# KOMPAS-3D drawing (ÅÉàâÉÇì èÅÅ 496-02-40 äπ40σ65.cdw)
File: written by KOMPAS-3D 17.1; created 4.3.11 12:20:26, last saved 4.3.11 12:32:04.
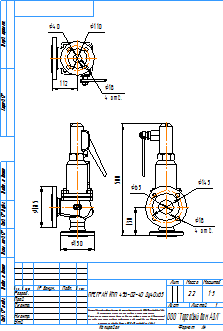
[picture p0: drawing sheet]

Sheet 1: A4, portrait

Title block, sheet 1: name: ПРЕГРАН КПП 496-02-40 Ду40х65; mass: 22; sheets: 1; sheet format: A4; stored path: \\adlc.lan\data\АДЛ_ПКД\3D-модели\ADL production\Предохранительные клапаны ПРЕГРАН\ПРЕГРАН 496\ПРЕГРАН КПП 496-02-40\KOMPAS 2D\ПРЕГРАН КПП 496-02-40 Ду40х65.cdw

Views: Спереди 1, Проекционный вид 2, Проекционный вид 3
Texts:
  Рама для чертежей
  Лит-Масса-Масштаб
  Материал-Предприятие
  Масштаб
  Изм.
  Лист
  № докум.
  Подп.
  Дата
  Лит.
  Разраб.
  Пров.
  Т.контр.
  Листов
  Внимание! Данный продукт является объектом авторского права ООО «Торговый Дом АДЛ».
  Запрещается изменение, копирование, распространение
  (в том числе путем копирования на другие сайты и ресурсы в Интернете)
  или любое иное использование информации и объектов без предварительного
  согласия правообладателя (ООО «Торговый Дом АДЛ»).
  Н.контр.
  Утв.
  ООО "Торговый дом АДЛ"
  Изменение
  Номер документа
  Подпись
  Обозначение документа
  Наименование изделия
  Масса изделия по ГОСТ 2.109-73
  Порядковый номер листа
  Общее количество листов в документе
  Характер работы, выполненной лицом, подписавшим документ
  Наименование или индекс предприятия, выпускающего документ
  Инв. № подл.
  Подп. и дата
  Взам. инв. №
  Инв. № дубл.
  Инвентарный номер подлинника по ГОСТ 2.501-68
  Подпись принявшего подлинник в отдел технической документации
  Инвентарный номер подлинника, взамен которого выпущен данный подлинник
  Инвентарный номер дубликата по ГОСТ 2.502-68
  Подпись принявшего дубликат в отдел технической документации
  Справ. №
  Перв. примен.
  Обозначение документа, взамен или на основании которого выпущен данный документ
  Обозначение документа, в котором впервые записан данный документ
  Подпись лица, копировавшего чертеж
  Обозначение формата листа
  !Рама для чертежа
Dimensions and other numbers on the sheet: 185; 150; 500; 145; 65; 130; 18; 4 отв.; 112; 40; 110; 1:5; 1; 22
